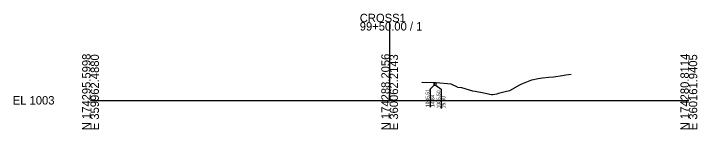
# Model space of a CAD drawing. Extents: x -26 to 1403, y -10 to 11027.
# Drawn here: x 1174.3 to 1402.8, y 2990.3 to 3029 of the extents above; entities that cross this region are included whole.
import ezdxf

# ---------------------------------------------------------------- set-up
doc = ezdxf.new("R2010")
doc.units = 0
for name, color, linetype in [('Default', 7, 'Continuous'), ('P_E_XS_Ground', 7, 'Continuous'), ('P_XS_EAR_CommonGrnd', 7, 'Continuous'), ('P_XS_Lane', 7, 'Continuous'), ('P_XS_Rock', 7, 'Continuous')]:
    doc.layers.add(name, color=color, linetype=linetype)

msp = doc.modelspace()

# ---------------------------------------------------------------- linework, layer by layer
at = {"layer": 'Default'}
for p, q in [((1300, 3000), (1300, 3026.14)), ((1200, 3000), (1300, 3000)), ((1300, 3000), (1400, 3000))]:
    msp.add_line(p, q, dxfattribs=at)
at = {"layer": 'P_E_XS_Ground'}
for p, q in [((1350.28, 3007.46), (1351.03, 3007.51)), ((1351.03, 3007.51), (1353.19, 3007.72)), ((1353.19, 3007.72), (1354.8, 3007.91)), ((1354.8, 3007.91), (1357.73, 3008.36)), ((1357.73, 3008.36), (1358.86, 3008.55)), ((1358.86, 3008.55), (1360.71, 3008.71)), ((1310.75, 3006.03), (1310.84, 3006.02)), ((1315.5, 3005.84), (1310.84, 3006.02)), ((1320.5, 3005.44), (1315.5, 3005.84)), ((1322.64, 3004.37), (1320.5, 3005.44)), ((1343.5, 3005.2), (1344.12, 3005.52)), ((1344.12, 3005.52), (1344.73, 3005.75)), ((1344.73, 3005.75), (1347.47, 3006.82)), ((1347.47, 3006.82), (1349.69, 3007.28)), ((1349.69, 3007.28), (1350.28, 3007.46)), ((1322.64, 3004.37), (1324.04, 3004.27)), ((1324.04, 3004.27), (1327.74, 3003.22)), ((1327.74, 3003.22), (1328.54, 3003.03)), ((1328.54, 3003.03), (1331.51, 3002.5)), ((1336.34, 3002.36), (1339.09, 3003.03)), ((1339.09, 3003.03), (1340.11, 3003.34)), ((1340.11, 3003.34), (1343.5, 3005.2)), ((1331.51, 3002.5), (1332.52, 3002.26)), ((1332.52, 3002.26), (1334.02, 3001.97)), ((1334.02, 3001.97), (1334.44, 3001.95)), ((1334.44, 3001.95), (1335.89, 3002.23)), ((1335.89, 3002.23), (1336.34, 3002.36))]:
    msp.add_line(p, q, dxfattribs=at)
at = {"layer": 'P_XS_EAR_CommonGrnd'}
msp.add_lwpolyline([(1315.5, 3005.84), (1314.84, 3005.86), (1314.84, 3005.03), (1315.5, 3005)], close=True, dxfattribs=at)
at = {"layer": 'P_XS_Lane'}
for p, q in [((1314.84, 3005.03), (1314.84, 3005.86)), ((1315.5, 3005), (1315.5, 3005.84)), ((1314.84, 3005.03), (1315.5, 3005))]:
    msp.add_line(p, q, dxfattribs=at)
at = {"layer": 'P_XS_Rock'}
for p, q in [((1313.48, 3003.79), (1314.78, 3004.97)), ((1313.48, 3003.79), (1313.48, 2997.74)), ((1315.56, 3004.96), (1317.17, 3003.77)), ((1317.17, 3003.77), (1317.17, 2997.32))]:
    msp.add_line(p, q, dxfattribs=at)

# ---------------------------------------------------------------- texts
at = {"layer": 'Default'}
for s, p in [('CROSS1', (1290, 3026.14)), ('99+50.00 / 1', (1290, 3023.34)), ('EL 1003', (1174, 2998.6))]:
    msp.add_text(s, height=2.8, dxfattribs=at).set_placement(p)
for s, p in [('N 174295.5998', (1200, 2990)), ('E 359962.4880', (1202.8, 2990)), ('N 174288.2056', (1300, 2990)), ('E 360062.2143', (1302.8, 2990)), ('N 174280.8114', (1400, 2990)), ('E 360161.9405', (1402.8, 2990))]:
    msp.add_text(s, height=2.8, rotation=90, dxfattribs=at).set_placement(p)
at = {"layer": 'P_XS_Rock'}
for s, p in [('1005.51', (1313.23, 2997.74)), ('1005.50', (1316.92, 2997.32)), ('14.84', (1314.93, 2997.74)), ('15.50', (1318.62, 2997.32))]:
    msp.add_text(s, height=1.2, rotation=90, dxfattribs=at).set_placement(p)

doc.saveas('drawing.dxf')
